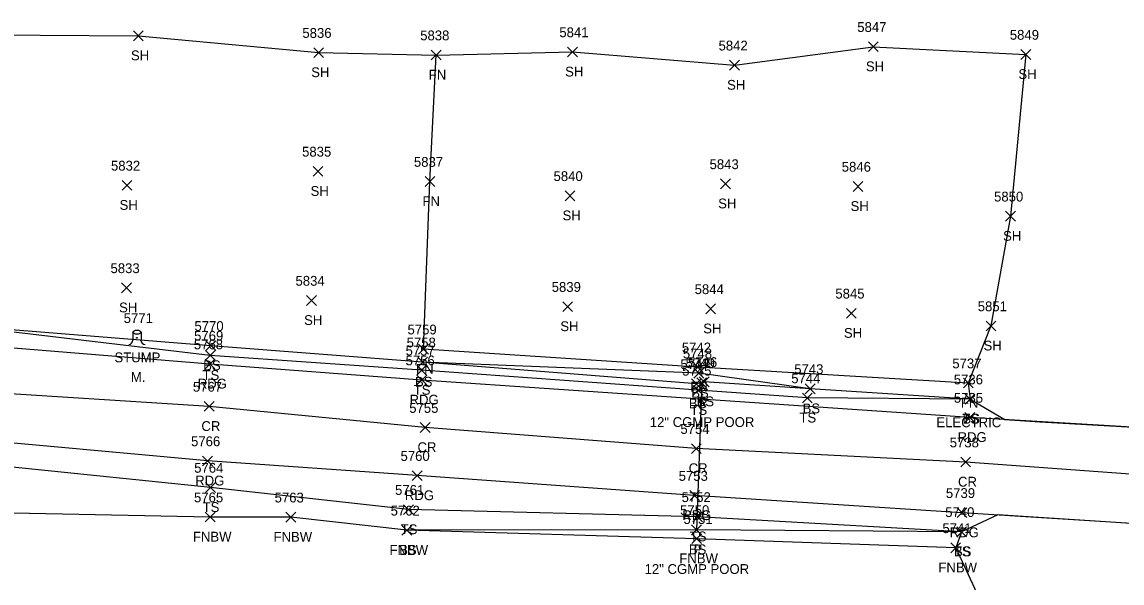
# Model space of a CAD drawing. Extents: x 1472233 to 1475777, y 540726 to 543442.
# Drawn here: x 1472552.6 to 1472776.8, y 541852.8 to 541967.1 of the extents above; entities that cross this region are included whole.
import ezdxf

# ---------------------------------------------------------------- set-up
doc = ezdxf.new("R2010")
doc.units = 0
for name, color, linetype in [('D_A', 7, 'Continuous'), ('D_C', 7, 'Continuous'), ('D_I', 7, 'Continuous'), ('D_TIC', 7, 'Continuous'), ('DCP', 7, 'Continuous'), ('L_A', 7, 'Continuous'), ('L_C', 7, 'Continuous'), ('L_I', 7, 'Continuous'), ('L_TIC', 7, 'Continuous'), ('LELB', 7, 'Continuous'), ('LFNC', 7, 'Continuous'), ('LSOGP', 7, 'Continuous'), ('LTS', 7, 'Continuous'), ('P_A', 7, 'Continuous'), ('P_I', 7, 'Continuous'), ('P_TIC', 7, 'Continuous'), ('PEU', 7, 'Continuous'), ('PRC', 7, 'Continuous')]:
    doc.layers.add(name, color=color, linetype=linetype)

msp = doc.modelspace()

# ---------------------------------------------------------------- linework, layer by layer
at = {"layer": 'D_TIC'}
for points in [[(1472690.18, 541892.63), (1472692.18, 541894.63)], [(1472692.18, 541892.63), (1472690.18, 541894.63)], [(1472689.12, 541862.69), (1472691.12, 541864.69)], [(1472691.12, 541862.69), (1472689.12, 541864.69)]]:
    msp.add_lwpolyline(points, dxfattribs=at)
at = {"layer": 'DCP'}
msp.add_lwpolyline([(1472691.18, 541893.63), (1472690.12, 541863.69)], dxfattribs=at)
at = {"layer": 'L_TIC'}
for points in [[(1472575.35, 541963.34), (1472577.35, 541965.34)], [(1472577.35, 541963.34), (1472575.35, 541965.34)], [(1472612.09, 541959.91), (1472614.09, 541961.91)], [(1472614.09, 541959.91), (1472612.09, 541961.91)], [(1472663.85, 541960.04), (1472665.85, 541962.04)], [(1472665.85, 541960.04), (1472663.85, 541962.04)], [(1472725.15, 541961.11), (1472727.15, 541963.11)], [(1472727.15, 541961.11), (1472725.15, 541963.11)], [(1472756.25, 541959.53), (1472758.25, 541961.53)], [(1472758.25, 541959.53), (1472756.25, 541961.53)], [(1472636.06, 541959.41), (1472638.06, 541961.41)], [(1472638.06, 541959.41), (1472636.06, 541961.41)], [(1472696.87, 541957.34), (1472698.87, 541959.34)], [(1472698.87, 541957.34), (1472696.87, 541959.34)], [(1472611.98, 541935.72), (1472613.98, 541937.72)], [(1472613.98, 541935.72), (1472611.98, 541937.72)], [(1472573.03, 541932.87), (1472575.03, 541934.87)], [(1472575.03, 541932.87), (1472573.03, 541934.87)], [(1472634.78, 541933.64), (1472636.78, 541935.64)], [(1472636.78, 541933.64), (1472634.78, 541935.64)], [(1472695.04, 541933.17), (1472697.04, 541935.17)], [(1472697.04, 541933.17), (1472695.04, 541935.17)], [(1472722.03, 541932.64), (1472724.03, 541934.64)], [(1472724.03, 541932.64), (1472722.03, 541934.64)], [(1472663.32, 541930.74), (1472665.32, 541932.74)], [(1472665.32, 541930.74), (1472663.32, 541932.74)], [(1472753.12, 541926.57), (1472755.12, 541928.57)], [(1472755.12, 541926.57), (1472753.12, 541928.57)], [(1472572.93, 541911.98), (1472574.93, 541913.98)], [(1472574.93, 541911.98), (1472572.93, 541913.98)], [(1472610.64, 541909.41), (1472612.64, 541911.41)], [(1472612.64, 541909.41), (1472610.64, 541911.41)], [(1472662.87, 541908.16), (1472664.87, 541910.16)], [(1472664.87, 541908.16), (1472662.87, 541910.16)], [(1472692, 541907.7), (1472694, 541909.7)], [(1472694, 541907.7), (1472692, 541909.7)], [(1472720.68, 541906.8), (1472722.68, 541908.8)], [(1472722.68, 541906.8), (1472720.68, 541908.8)], [(1472749.13, 541904.22), (1472751.13, 541906.22)], [(1472751.13, 541904.22), (1472749.13, 541906.22)], [(1472590.12, 541900.19), (1472592.12, 541902.19)], [(1472592.12, 541900.19), (1472590.12, 541902.19)], [(1472633.47, 541899.49), (1472635.47, 541901.49)], [(1472635.47, 541899.49), (1472633.47, 541901.49)], [(1472590.02, 541898.21), (1472592.02, 541900.21)], [(1472592.02, 541898.21), (1472590.02, 541900.21)], [(1472633.29, 541896.84), (1472635.29, 541898.84)], [(1472635.29, 541896.84), (1472633.29, 541898.84)], [(1472633.29, 541896.84), (1472635.29, 541898.84)], [(1472635.29, 541896.84), (1472633.29, 541898.84)], [(1472633.08, 541895.2), (1472635.08, 541897.2)], [(1472635.08, 541895.2), (1472633.08, 541897.2)], [(1472689.39, 541895.83), (1472691.39, 541897.83)], [(1472691.39, 541895.83), (1472689.39, 541897.83)], [(1472689.6, 541894.59), (1472691.6, 541896.59)], [(1472691.6, 541894.59), (1472689.6, 541896.59)], [(1472689.1, 541892.43), (1472691.1, 541894.43)], [(1472691.1, 541892.43), (1472689.1, 541894.43)], [(1472690.69, 541892.84), (1472692.69, 541894.84)], [(1472692.69, 541892.84), (1472690.69, 541894.84)], [(1472744.52, 541892.58), (1472746.52, 541894.58)], [(1472746.52, 541892.58), (1472744.52, 541894.58)], [(1472689.47, 541891.1), (1472691.47, 541893.1)], [(1472691.47, 541891.1), (1472689.47, 541893.1)], [(1472712.3, 541891.41), (1472714.3, 541893.41)], [(1472714.3, 541891.41), (1472712.3, 541893.41)], [(1472712.3, 541891.41), (1472714.3, 541893.41)], [(1472714.3, 541891.41), (1472712.3, 541893.41)], [(1472711.69, 541889.54), (1472713.69, 541891.54)], [(1472713.69, 541889.54), (1472711.69, 541891.54)], [(1472744.87, 541889.31), (1472746.87, 541891.31)], [(1472746.87, 541889.31), (1472744.87, 541891.31)], [(1472744.87, 541889.31), (1472746.87, 541891.31)], [(1472746.87, 541889.31), (1472744.87, 541891.31)], [(1472590.04, 541871.31), (1472592.04, 541873.31)], [(1472592.04, 541871.31), (1472590.04, 541873.31)], [(1472590, 541865.28), (1472592, 541867.28)], [(1472592, 541865.28), (1472590, 541867.28)], [(1472630.41, 541866.8), (1472632.41, 541868.8)], [(1472632.41, 541866.8), (1472630.41, 541868.8)], [(1472689.34, 541865.33), (1472691.34, 541867.33)], [(1472691.34, 541865.33), (1472689.34, 541867.33)], [(1472606.43, 541865.25), (1472608.43, 541867.25)], [(1472608.43, 541865.25), (1472606.43, 541867.25)], [(1472630.07, 541862.58), (1472632.07, 541864.58)], [(1472632.07, 541862.58), (1472630.07, 541864.58)], [(1472630.07, 541862.58), (1472632.07, 541864.58)], [(1472632.07, 541862.58), (1472630.07, 541864.58)], [(1472689.12, 541862.69), (1472691.12, 541864.69)], [(1472691.12, 541862.69), (1472689.12, 541864.69)], [(1472689.14, 541860.86), (1472691.14, 541862.86)], [(1472691.14, 541860.86), (1472689.14, 541862.86)], [(1472743.15, 541862.28), (1472745.15, 541864.28)], [(1472745.15, 541862.28), (1472743.15, 541864.28)], [(1472743.15, 541862.28), (1472745.15, 541864.28)], [(1472745.15, 541862.28), (1472743.15, 541864.28)], [(1472741.95, 541859), (1472743.95, 541861)], [(1472743.95, 541859), (1472741.95, 541861)]]:
    msp.add_lwpolyline(points, dxfattribs=at)
at = {"layer": 'LELB'}
for points in [[(1472745.87, 541890.31), (1472712.69, 541890.54), (1472690.47, 541892.1), (1472634.08, 541896.2), (1472591.02, 541899.21), (1472539.39, 541905.34), (1472514.36, 541915.84), (1472487.44, 541916.39), (1472464.21, 541915.48), (1472453.82, 541918.91), (1472444.32, 541929.84), (1472439.04, 541948)], [(1472745.87, 541890.31), (1472713.3, 541892.41), (1472691.69, 541893.84), (1472690.1, 541893.43), (1472634.29, 541897.84), (1472591.12, 541901.19), (1472539.39, 541905.34), (1472512.97, 541908.18), (1472487.6, 541907.91), (1472463.59, 541911.27), (1472451.45, 541916.4)], [(1472713.3, 541892.41), (1472690.6, 541895.59), (1472634.29, 541897.84)], [(1472744.15, 541863.28), (1472690.34, 541866.33), (1472631.41, 541867.8), (1472591.04, 541872.31), (1472538.06, 541877.71), (1472512.26, 541876.18), (1472493.65, 541872.21), (1472479.41, 541862.64)], [(1472744.15, 541863.28), (1472690.12, 541863.69), (1472631.07, 541863.58)]]:
    msp.add_lwpolyline(points, dxfattribs=at)
at = {"layer": 'LFNC'}
for points in [[(1472745.52, 541893.58), (1472690.39, 541896.83), (1472634.47, 541900.49), (1472635.78, 541934.64), (1472637.06, 541960.41)], [(1472742.95, 541860), (1472690.14, 541861.86), (1472631.07, 541863.58), (1472607.43, 541866.25), (1472591, 541866.28), (1472540.71, 541867.28)]]:
    msp.add_lwpolyline(points, dxfattribs=at)
at = {"layer": 'LSOGP'}
for points in [[(1472536.25, 541964.58), (1472576.35, 541964.34), (1472613.09, 541960.91), (1472637.06, 541960.41), (1472664.85, 541961.04), (1472697.87, 541958.34), (1472726.15, 541962.11), (1472757.25, 541960.53), (1472754.12, 541927.57), (1472750.13, 541905.22), (1472745.52, 541893.58), (1472745.87, 541890.31), (1472752.97, 541886.14), (1472760.09, 541885.71), (1472767.22, 541885.28), (1472774.35, 541884.86), (1472781.48, 541884.43)], [(1472780.75, 541864.86), (1472773.45, 541865.32), (1472766.14, 541865.78), (1472758.83, 541866.24), (1472751.53, 541866.7), (1472744.15, 541863.28), (1472742.95, 541860), (1472750.96, 541842.72), (1472769.66, 541814.65), (1472800.05, 541799.35)]]:
    msp.add_lwpolyline(points, dxfattribs=at)
at = {"layer": 'LTS'}
for p, q in [((1472575.22, 541903.95), (1472575.22, 541902.29)), ((1472576.89, 541903.79), (1472576.89, 541903.95)), ((1472576.89, 541903.95), (1472576.89, 541902.29)), ((1472576.06, 541902.81), (1472576.06, 541902.81)), ((1472576.06, 541902.81), (1472576.06, 541902.81)), ((1472576.06, 541902.79), (1472576.06, 541902.79))]:
    msp.add_line(p, q, dxfattribs=at)
msp.add_circle((1472576.06, 541902.81), 0.0833, dxfattribs=at)
for centre, start, end in [((1472574.39, 541902.29), 270, 360), ((1472577.72, 541902.29), 180, 270)]:
    msp.add_arc(centre, 0.833, start, end, dxfattribs=at)
msp.add_ellipse((1472576.06, 541903.95), major_axis=(-0.833, 0), ratio=0.5, dxfattribs=at)
at = {"layer": 'P_TIC'}
for points in [[(1472589.96, 541896.46), (1472591.96, 541898.46)], [(1472591.96, 541896.46), (1472589.96, 541898.46)], [(1472633.14, 541893.19), (1472635.14, 541895.19)], [(1472635.14, 541893.19), (1472633.14, 541895.19)], [(1472589.77, 541887.82), (1472591.77, 541889.82)], [(1472591.77, 541887.82), (1472589.77, 541889.82)], [(1472744.84, 541885.57), (1472746.84, 541887.57)], [(1472746.84, 541885.57), (1472744.84, 541887.57)], [(1472633.82, 541883.51), (1472635.82, 541885.51)], [(1472635.82, 541883.51), (1472633.82, 541885.51)], [(1472689.08, 541879.23), (1472691.08, 541881.23)], [(1472691.08, 541879.23), (1472689.08, 541881.23)], [(1472589.45, 541876.71), (1472591.45, 541878.71)], [(1472591.45, 541876.71), (1472589.45, 541878.71)], [(1472743.99, 541876.48), (1472745.99, 541878.48)], [(1472745.99, 541876.48), (1472743.99, 541878.48)], [(1472632.19, 541873.72), (1472634.19, 541875.72)], [(1472634.19, 541873.72), (1472632.19, 541875.72)], [(1472688.74, 541869.66), (1472690.74, 541871.66)], [(1472690.74, 541869.66), (1472688.74, 541871.66)], [(1472743.22, 541866.16), (1472745.22, 541868.16)], [(1472745.22, 541866.16), (1472743.22, 541868.16)]]:
    msp.add_lwpolyline(points, dxfattribs=at)
at = {"layer": 'PEU'}
for points in [[(1473098.91, 541964.62), (1473089.43, 541936.62), (1473074.38, 541914.75), (1473056.61, 541898.09), (1473030.47, 541883.54), (1472996.76, 541875.47), (1472956.5, 541874.15), (1472908.55, 541875.95), (1472855.73, 541879.37), (1472802.86, 541883.15), (1472745.84, 541886.57), (1472634.14, 541894.19), (1472590.96, 541897.46), (1472539.16, 541901.65), (1472512.37, 541903.04), (1472487.81, 541903.86), (1472463.66, 541907.57), (1472451.45, 541916.4), (1472440.19, 541926.31)], [(1473120.03, 541958.16), (1473109.34, 541927.18), (1473091.19, 541896.62), (1473071.69, 541877.42), (1473038.14, 541861.81), (1473000.67, 541854.62), (1472955, 541854.82), (1472907.73, 541856.6), (1472854.8, 541860.38), (1472802.67, 541863.47), (1472744.22, 541867.16), (1472689.74, 541870.66), (1472633.19, 541874.72), (1472590.45, 541877.71), (1472538.25, 541882.48), (1472511.32, 541881.1), (1472493.14, 541878.09), (1472476.04, 541867.78), (1472470.9, 541847.46)]]:
    msp.add_lwpolyline(points, dxfattribs=at)
at = {"layer": 'PRC'}
msp.add_lwpolyline([(1473109.08, 541961.17), (1473099.3, 541931.88), (1473082.74, 541906.14), (1473064.38, 541887.7), (1473033.58, 541873.25), (1472998.66, 541865.24), (1472955.43, 541864.43), (1472908.09, 541866.27), (1472855.6, 541870.36), (1472802.7, 541873.24), (1472744.99, 541877.48), (1472690.08, 541880.23), (1472634.82, 541884.51), (1472590.77, 541888.82), (1472538.5, 541892.13), (1472513.15, 541892.78), (1472490.32, 541890.8), (1472467.35, 541887.63), (1472454.88, 541886.72)], dxfattribs=at)

# ---------------------------------------------------------------- texts
at = {"layer": 'D_A'}
for p in [(1472690.55, 541888.63), (1472689.5, 541858.69)]:
    msp.add_text('P', height=2, dxfattribs=at).set_placement(p)
at = {"layer": 'D_C'}
for p in [(1472680.6, 541884.63), (1472679.54, 541854.69)]:
    msp.add_text('12" CGMP POOR', height=2, dxfattribs=at).set_placement(p)
at = {"layer": 'D_I'}
for s, p in [('5749', (1472687.91, 541896.63)), ('5750', (1472686.77, 541866.69))]:
    msp.add_text(s, height=2, dxfattribs=at).set_placement(p)
at = {"layer": 'L_A'}
for s, p in [('SH', (1472574.84, 541959.34)), ('SH', (1472611.58, 541955.91)), ('FN', (1472635.54, 541955.41)), ('SH', (1472663.34, 541956.04)), ('SH', (1472724.64, 541957.11)), ('SH', (1472755.73, 541955.53)), ('SH', (1472696.35, 541953.34)), ('SH', (1472611.46, 541931.72)), ('SH', (1472572.52, 541928.87)), ('FN', (1472634.26, 541929.64)), ('SH', (1472694.53, 541929.17)), ('SH', (1472721.52, 541928.64)), ('SH', (1472662.81, 541926.74)), ('SH', (1472752.61, 541922.57)), ('SH', (1472572.42, 541907.98)), ('SH', (1472610.13, 541905.41)), ('SH', (1472662.36, 541904.16)), ('SH', (1472691.49, 541903.7)), ('SH', (1472720.17, 541902.8)), ('SH', (1472748.62, 541900.22)), ('STUMP', (1472571.48, 541897.81)), ('BS', (1472589.56, 541896.19)), ('FN', (1472632.96, 541895.49)), ('TS', (1472589.43, 541894.21)), ('BS', (1472632.73, 541892.84)), ('BS', (1472632.73, 541892.84)), ('TS', (1472632.48, 541891.2)), ('FN', (1472688.87, 541891.83)), ('BS', (1472689.04, 541890.59)), ('BS', (1472688.54, 541888.43)), ('BS', (1472690.13, 541888.84)), ('FN', (1472744, 541888.58)), ('TS', (1472688.88, 541887.1)), ('TS', (1472711.1, 541885.54)), ('BS', (1472711.74, 541887.41)), ('BS', (1472711.74, 541887.41)), ('TS', (1472744.28, 541885.31)), ('BS', (1472744.32, 541885.31)), ('TS', (1472589.45, 541867.31)), ('FNBW', (1472587.47, 541861.28)), ('FNBW', (1472603.9, 541861.25)), ('TS', (1472629.82, 541862.8)), ('TS', (1472688.75, 541861.33)), ('FNBW', (1472627.54, 541858.58)), ('BS', (1472629.51, 541858.58)), ('BS', (1472688.56, 541858.69)), ('FNBW', (1472686.61, 541856.86)), ('TS', (1472742.56, 541858.28)), ('BS', (1472742.59, 541858.28)), ('FNBW', (1472739.42, 541855))]:
    msp.add_text(s, height=2, dxfattribs=at).set_placement(p)
at = {"layer": 'L_C'}
for s, p in [('M.', (1472574.82, 541893.81)), ('ELECTRIC', (1472739.01, 541884.58))]:
    msp.add_text(s, height=2, dxfattribs=at).set_placement(p)
at = {"layer": 'L_I'}
for s, p in [('5836', (1472609.78, 541963.91)), ('5841', (1472662.16, 541964.04)), ('5847', (1472722.89, 541965.11)), ('5838', (1472633.8, 541963.41)), ('5849', (1472753.98, 541963.53)), ('5842', (1472694.61, 541961.34)), ('5835', (1472609.72, 541939.72)), ('5837', (1472632.52, 541937.64)), ('5843', (1472692.78, 541937.17)), ('5832', (1472570.77, 541936.87)), ('5840', (1472660.98, 541934.74)), ('5846', (1472719.72, 541936.64)), ('5850', (1472750.77, 541930.57)), ('5833', (1472570.67, 541915.98)), ('5834', (1472608.38, 541913.41)), ('5839', (1472660.6, 541912.16)), ('5844', (1472689.74, 541911.7)), ('5845', (1472718.42, 541910.8)), ('5851', (1472747.44, 541908.22)), ('5771', (1472573.36, 541905.81)), ('5770', (1472587.78, 541904.19)), ('5759', (1472631.21, 541903.49)), ('5769', (1472587.71, 541902.21)), ('5757', (1472630.82, 541899.2)), ('5758', (1472631.03, 541900.84)), ('5758', (1472631.03, 541900.84)), ('5742', (1472687.13, 541899.83)), ('5748', (1472687.34, 541898.59)), ('5746', (1472688.38, 541896.84)), ('5747', (1472686.84, 541896.43)), ('5745', (1472687.21, 541895.1)), ('5743', (1472710.04, 541895.41)), ('5743', (1472710.04, 541895.41)), ('5737', (1472742.26, 541896.58)), ('5744', (1472709.43, 541893.54)), ('5736', (1472742.56, 541893.31)), ('5736', (1472742.56, 541893.31)), ('5764', (1472587.73, 541875.31)), ('5761', (1472628.67, 541870.8)), ('5765', (1472587.69, 541869.28)), ('5763', (1472604.12, 541869.25)), ('5752', (1472687.08, 541869.33)), ('5762', (1472627.77, 541866.58)), ('5762', (1472627.77, 541866.58)), ('5750', (1472686.77, 541866.69)), ('5740', (1472740.81, 541866.28)), ('5740', (1472740.81, 541866.28)), ('5751', (1472687.45, 541864.86)), ('5741', (1472740.25, 541863))]:
    msp.add_text(s, height=2, dxfattribs=at).set_placement(p)
at = {"layer": 'P_A'}
for s, p in [('RDG', (1472588.45, 541892.46)), ('RDG', (1472631.63, 541889.19)), ('CR', (1472589.2, 541883.82)), ('RDG', (1472743.33, 541881.57)), ('CR', (1472633.25, 541879.51)), ('CR', (1472688.52, 541875.23)), ('RDG', (1472587.94, 541872.71)), ('CR', (1472743.42, 541872.48)), ('RDG', (1472630.67, 541869.72)), ('RDG', (1472687.22, 541865.66)), ('RDG', (1472741.71, 541862.16))]:
    msp.add_text(s, height=2, dxfattribs=at).set_placement(p)
at = {"layer": 'P_I'}
for s, p in [('5768', (1472587.66, 541900.46)), ('5756', (1472630.82, 541897.19)), ('5767', (1472587.46, 541891.82)), ('5735', (1472742.58, 541889.57)), ('5755', (1472631.56, 541887.51)), ('5754', (1472686.83, 541883.23)), ('5766', (1472587.09, 541880.71)), ('5738', (1472741.73, 541880.48)), ('5760', (1472629.79, 541877.72)), ('5753', (1472686.48, 541873.66)), ('5739', (1472740.95, 541870.16))]:
    msp.add_text(s, height=2, dxfattribs=at).set_placement(p)

doc.saveas('drawing.dxf')
